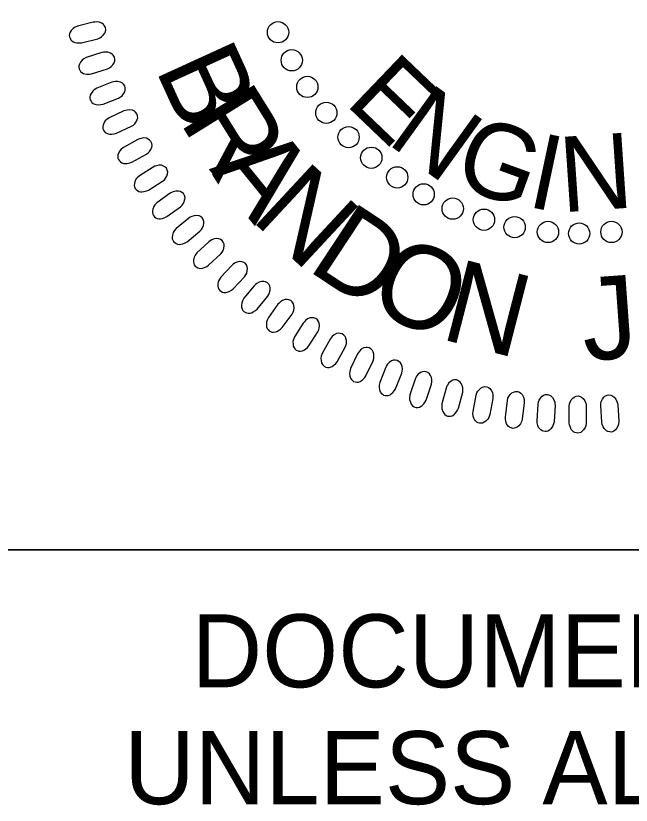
# Model space of a CAD drawing. Extents: x 505602 to 527661, y 418813 to 494436.
# Drawn here: x 507076.9 to 507123.2, y 484026.9 to 484086.4 of the extents above; entities that cross this region are included whole.
import ezdxf

# ---------------------------------------------------------------- set-up
doc = ezdxf.new("R2010")
doc.units = 0
for name, color, linetype in [('Sheet PE Seal Cell', 7, 'Continuous'), ('Sheet Profile CELL', 7, 'Continuous'), ('Sheet Sticker Exception Certification CELL', 7, 'Continuous')]:
    doc.layers.add(name, color=color, linetype=linetype)

msp = doc.modelspace()

# ---------------------------------------------------------------- linework, layer by layer
at = {"layer": 'Sheet PE Seal Cell'}
for points in [[(507082.689, 484085.9), (507081.501, 484085.595), (507081.298, 484085.504), (507081.175, 484085.42), (507081.039, 484085.269), (507080.957, 484085.147), (507080.907, 484085.019), (507080.895, 484084.908), (507080.903, 484084.794), (507080.95, 484084.691), (507081.009, 484084.582), (507081.093, 484084.495), (507081.216, 484084.419), (507081.308, 484084.38), (507081.469, 484084.353), (507081.658, 484084.339), (507081.818, 484084.357), (507083.037, 484084.662), (507083.196, 484084.726), (507083.32, 484084.804), (507083.452, 484084.931), (507083.56, 484085.074), (507083.613, 484085.187), (507083.632, 484085.355), (507083.614, 484085.505), (507083.538, 484085.639), (507083.464, 484085.728), (507083.336, 484085.827), (507083.142, 484085.9), (507082.951, 484085.921), (507082.818, 484085.917)], [(507083.343, 484083.616), (507082.176, 484083.237), (507081.979, 484083.134), (507081.862, 484083.042), (507081.735, 484082.882), (507081.661, 484082.756), (507081.62, 484082.625), (507081.615, 484082.513), (507081.63, 484082.4), (507081.684, 484082.3), (507081.749, 484082.195), (507081.838, 484082.114), (507081.966, 484082.046), (507082.059, 484082.013), (507082.223, 484081.995), (507082.412, 484081.994), (507082.571, 484082.022), (507083.768, 484082.403), (507083.922, 484082.477), (507084.042, 484082.562), (507084.165, 484082.697), (507084.263, 484082.846), (507084.31, 484082.963), (507084.318, 484083.131), (507084.291, 484083.28), (507084.207, 484083.409), (507084.127, 484083.494), (507083.993, 484083.584), (507083.795, 484083.645), (507083.603, 484083.654), (507083.471, 484083.642)], [(507084.102, 484081.379), (507082.961, 484080.928), (507082.77, 484080.812), (507082.659, 484080.713), (507082.543, 484080.546), (507082.477, 484080.415), (507082.444, 484080.281), (507082.446, 484080.17), (507082.468, 484080.058), (507082.528, 484079.961), (507082.6, 484079.861), (507082.693, 484079.786), (507082.825, 484079.725), (507082.921, 484079.699), (507083.086, 484079.691), (507083.274, 484079.702), (507083.431, 484079.739), (507084.602, 484080.194), (507084.752, 484080.278), (507084.865, 484080.371), (507084.98, 484080.513), (507085.069, 484080.668), (507085.108, 484080.788), (507085.105, 484080.956), (507085.069, 484081.103), (507084.977, 484081.227), (507084.892, 484081.306), (507084.753, 484081.388), (507084.551, 484081.436), (507084.359, 484081.433), (507084.228, 484081.412)], [(507085.001, 484079.22), (507083.891, 484078.698), (507083.709, 484078.57), (507083.604, 484078.464), (507083.499, 484078.29), (507083.441, 484078.155), (507083.416, 484078.02), (507083.425, 484077.908), (507083.454, 484077.798), (507083.52, 484077.706), (507083.598, 484077.61), (507083.697, 484077.541), (507083.832, 484077.489), (507083.929, 484077.468), (507084.093, 484077.471), (507084.281, 484077.494), (507084.435, 484077.541), (507085.576, 484078.068), (507085.719, 484078.161), (507085.827, 484078.261), (507085.932, 484078.41), (507086.012, 484078.571), (507086.043, 484078.693), (507086.03, 484078.861), (507085.984, 484079.005), (507085.884, 484079.122), (507085.794, 484079.196), (507085.651, 484079.269), (507085.446, 484079.304), (507085.255, 484079.289), (507085.125, 484079.261)], [(507086.049, 484077.071), (507084.973, 484076.48), (507084.799, 484076.342), (507084.702, 484076.229), (507084.607, 484076.049), (507084.558, 484075.91), (507084.542, 484075.774), (507084.557, 484075.663), (507084.594, 484075.555), (507084.666, 484075.467), (507084.75, 484075.377), (507084.852, 484075.314), (507084.99, 484075.27), (507085.089, 484075.256), (507085.252, 484075.269), (507085.438, 484075.303), (507085.589, 484075.36), (507086.694, 484075.958), (507086.832, 484076.06), (507086.932, 484076.167), (507087.029, 484076.322), (507087.097, 484076.487), (507087.121, 484076.611), (507087.097, 484076.777), (507087.043, 484076.918), (507086.936, 484077.03), (507086.842, 484077.098), (507086.693, 484077.161), (507086.487, 484077.184), (507086.297, 484077.156), (507086.169, 484077.12)], [(507087.205, 484074.996), (507086.169, 484074.339), (507086.003, 484074.19), (507085.914, 484074.072), (507085.83, 484073.885), (507085.79, 484073.745), (507085.783, 484073.607), (507085.805, 484073.498), (507085.848, 484073.392), (507085.926, 484073.309), (507086.015, 484073.224), (507086.121, 484073.167), (507086.261, 484073.132), (507086.36, 484073.124), (507086.523, 484073.148), (507086.707, 484073.194), (507086.853, 484073.26), (507087.919, 484073.926), (507088.05, 484074.036), (507088.144, 484074.15), (507088.23, 484074.31), (507088.288, 484074.479), (507088.304, 484074.605), (507088.27, 484074.769), (507088.207, 484074.906), (507088.093, 484075.011), (507087.995, 484075.072), (507087.842, 484075.126), (507087.635, 484075.137), (507087.447, 484075.097), (507087.322, 484075.053)], [(507088.482, 484073.021), (507087.488, 484072.3), (507087.333, 484072.141), (507087.25, 484072.017), (507087.179, 484071.826), (507087.148, 484071.683), (507087.149, 484071.546), (507087.178, 484071.438), (507087.228, 484071.335), (507087.31, 484071.256), (507087.405, 484071.177), (507087.515, 484071.127), (507087.657, 484071.102), (507087.756, 484071.1), (507087.917, 484071.133), (507088.097, 484071.19), (507088.24, 484071.266), (507089.261, 484071.998), (507089.385, 484072.116), (507089.471, 484072.235), (507089.548, 484072.401), (507089.595, 484072.573), (507089.603, 484072.699), (507089.559, 484072.861), (507089.487, 484072.994), (507089.367, 484073.091), (507089.265, 484073.147), (507089.11, 484073.192), (507088.903, 484073.188), (507088.717, 484073.137), (507088.595, 484073.085)], [(507089.885, 484071.14), (507088.939, 484070.358), (507088.794, 484070.19), (507088.72, 484070.061), (507088.661, 484069.866), (507088.638, 484069.721), (507088.648, 484069.584), (507088.684, 484069.478), (507088.74, 484069.379), (507088.827, 484069.305), (507088.926, 484069.232), (507089.039, 484069.189), (507089.182, 484069.173), (507089.282, 484069.177), (507089.44, 484069.221), (507089.616, 484069.289), (507089.754, 484069.373), (507090.727, 484070.168), (507090.844, 484070.293), (507090.922, 484070.417), (507090.988, 484070.588), (507091.025, 484070.763), (507091.024, 484070.889), (507090.97, 484071.048), (507090.89, 484071.176), (507090.764, 484071.265), (507090.659, 484071.314), (507090.501, 484071.349), (507090.295, 484071.333), (507090.113, 484071.271), (507089.994, 484071.211)], [(507091.395, 484069.369), (507090.5, 484068.53), (507090.366, 484068.353), (507090.3, 484068.219), (507090.253, 484068.021), (507090.24, 484067.875), (507090.258, 484067.739), (507090.301, 484067.635), (507090.363, 484067.54), (507090.454, 484067.472), (507090.558, 484067.405), (507090.673, 484067.37), (507090.818, 484067.362), (507090.916, 484067.372), (507091.072, 484067.426), (507091.244, 484067.505), (507091.375, 484067.597), (507092.296, 484068.452), (507092.405, 484068.585), (507092.476, 484068.713), (507092.531, 484068.887), (507092.556, 484069.065), (507092.548, 484069.19), (507092.484, 484069.346), (507092.396, 484069.468), (507092.265, 484069.55), (507092.157, 484069.592), (507091.997, 484069.617), (507091.792, 484069.588), (507091.614, 484069.514), (507091.5, 484069.447)], [(507093.131, 484067.591), (507092.29, 484066.697), (507092.167, 484066.512), (507092.11, 484066.374), (507092.075, 484066.174), (507092.071, 484066.026), (507092.098, 484065.892), (507092.147, 484065.792), (507092.215, 484065.7), (507092.31, 484065.638), (507092.419, 484065.578), (507092.535, 484065.549), (507092.68, 484065.551), (507092.778, 484065.568), (507092.93, 484065.631), (507093.096, 484065.721), (507093.222, 484065.821), (507094.088, 484066.733), (507094.187, 484066.871), (507094.25, 484067.004), (507094.294, 484067.181), (507094.308, 484067.36), (507094.292, 484067.484), (507094.219, 484067.636), (507094.123, 484067.753), (507093.987, 484067.826), (507093.876, 484067.861), (507093.716, 484067.876), (507093.513, 484067.834), (507093.34, 484067.749), (507093.23, 484067.675)], [(507094.821, 484066.061), (507094.038, 484065.116), (507093.927, 484064.923), (507093.878, 484064.782), (507093.856, 484064.58), (507093.862, 484064.433), (507093.897, 484064.3), (507093.952, 484064.203), (507094.026, 484064.115), (507094.124, 484064.06), (507094.236, 484064.007), (507094.354, 484063.986), (507094.499, 484063.997), (507094.596, 484064.019), (507094.743, 484064.092), (507094.903, 484064.192), (507095.023, 484064.3), (507095.83, 484065.264), (507095.921, 484065.409), (507095.974, 484065.546), (507096.008, 484065.725), (507096.011, 484065.904), (507095.986, 484066.028), (507095.903, 484066.174), (507095.801, 484066.285), (507095.661, 484066.349), (507095.547, 484066.377), (507095.386, 484066.381), (507095.187, 484066.327), (507095.019, 484066.232), (507094.914, 484066.151)], [(507096.601, 484064.66), (507095.88, 484063.668), (507095.781, 484063.469), (507095.741, 484063.325), (507095.732, 484063.121), (507095.747, 484062.975), (507095.79, 484062.845), (507095.851, 484062.751), (507095.93, 484062.669), (507096.033, 484062.62), (507096.148, 484062.574), (507096.267, 484062.56), (507096.41, 484062.58), (507096.506, 484062.608), (507096.648, 484062.691), (507096.802, 484062.8), (507096.914, 484062.916), (507097.659, 484063.928), (507097.74, 484064.078), (507097.786, 484064.218), (507097.808, 484064.399), (507097.8, 484064.578), (507097.767, 484064.7), (507097.676, 484064.841), (507097.566, 484064.945), (507097.422, 484065.001), (507097.308, 484065.021), (507097.147, 484065.016), (507096.95, 484064.949), (507096.79, 484064.843), (507096.69, 484064.756)], [(507098.503, 484063.247), (507097.846, 484062.211), (507097.759, 484062.006), (507097.728, 484061.86), (507097.732, 484061.657), (507097.756, 484061.513), (507097.808, 484061.385), (507097.874, 484061.295), (507097.959, 484061.218), (507098.063, 484061.175), (507098.181, 484061.136), (507098.301, 484061.131), (507098.443, 484061.159), (507098.536, 484061.194), (507098.673, 484061.284), (507098.82, 484061.403), (507098.924, 484061.526), (507099.604, 484062.583), (507099.676, 484062.738), (507099.713, 484062.88), (507099.723, 484063.063), (507099.703, 484063.241), (507099.663, 484063.36), (507099.564, 484063.495), (507099.448, 484063.592), (507099.3, 484063.638), (507099.185, 484063.652), (507099.025, 484063.637), (507098.833, 484063.558), (507098.679, 484063.442), (507098.585, 484063.349)], [(507100.521, 484062.032), (507099.93, 484060.957), (507099.857, 484060.747), (507099.835, 484060.599), (507099.852, 484060.396), (507099.884, 484060.253), (507099.944, 484060.129), (507100.016, 484060.044), (507100.105, 484059.972), (507100.212, 484059.936), (507100.332, 484059.904), (507100.452, 484059.906), (507100.592, 484059.944), (507100.683, 484059.984), (507100.814, 484060.083), (507100.953, 484060.212), (507101.05, 484060.34), (507101.662, 484061.438), (507101.723, 484061.597), (507101.751, 484061.742), (507101.75, 484061.924), (507101.72, 484062.101), (507101.673, 484062.218), (507101.564, 484062.346), (507101.442, 484062.435), (507101.292, 484062.472), (507101.176, 484062.479), (507101.017, 484062.453), (507100.831, 484062.362), (507100.685, 484062.237), (507100.596, 484062.138)], [(507102.58, 484060.925), (507102.058, 484059.815), (507101.998, 484059.601), (507101.986, 484059.452), (507102.015, 484059.251), (507102.056, 484059.11), (507102.124, 484058.991), (507102.201, 484058.91), (507102.295, 484058.844), (507102.404, 484058.815), (507102.525, 484058.79), (507102.645, 484058.8), (507102.783, 484058.846), (507102.871, 484058.892), (507102.995, 484058.999), (507103.126, 484059.136), (507103.215, 484059.27), (507103.757, 484060.404), (507103.808, 484060.568), (507103.827, 484060.713), (507103.814, 484060.895), (507103.773, 484061.069), (507103.718, 484061.183), (507103.602, 484061.304), (507103.474, 484061.386), (507103.323, 484061.414), (507103.206, 484061.413), (507103.049, 484061.377), (507102.869, 484061.275), (507102.732, 484061.14), (507102.65, 484061.036)], [(507104.708, 484059.917), (507104.256, 484058.776), (507104.21, 484058.559), (507104.207, 484058.41), (507104.249, 484058.21), (507104.298, 484058.073), (507104.374, 484057.957), (507104.456, 484057.882), (507104.553, 484057.822), (507104.664, 484057.799), (507104.787, 484057.783), (507104.906, 484057.799), (507105.04, 484057.854), (507105.125, 484057.906), (507105.243, 484058.02), (507105.364, 484058.165), (507105.444, 484058.305), (507105.914, 484059.471), (507105.956, 484059.637), (507105.965, 484059.783), (507105.941, 484059.964), (507105.888, 484060.135), (507105.827, 484060.246), (507105.703, 484060.359), (507105.571, 484060.433), (507105.418, 484060.45), (507105.302, 484060.442), (507105.147, 484060.397), (507104.974, 484060.283), (507104.845, 484060.141), (507104.77, 484060.032)], [(507106.917, 484059.015), (507106.537, 484057.848), (507106.505, 484057.628), (507106.511, 484057.479), (507106.565, 484057.283), (507106.624, 484057.149), (507106.706, 484057.038), (507106.793, 484056.968), (507106.894, 484056.914), (507107.006, 484056.899), (507107.13, 484056.89), (507107.247, 484056.914), (507107.378, 484056.977), (507107.459, 484057.034), (507107.57, 484057.156), (507107.682, 484057.308), (507107.753, 484057.453), (507108.149, 484058.645), (507108.18, 484058.814), (507108.18, 484058.96), (507108.144, 484059.14), (507108.081, 484059.307), (507108.013, 484059.413), (507107.882, 484059.519), (507107.746, 484059.584), (507107.592, 484059.592), (507107.477, 484059.576), (507107.325, 484059.522), (507107.159, 484059.398), (507107.039, 484059.247), (507106.971, 484059.133)], [(507109.25, 484058.342), (507108.944, 484057.154), (507108.926, 484056.933), (507108.941, 484056.784), (507109.008, 484056.591), (507109.074, 484056.461), (507109.164, 484056.356), (507109.255, 484056.291), (507109.358, 484056.244), (507109.472, 484056.236), (507109.595, 484056.235), (507109.711, 484056.266), (507109.837, 484056.337), (507109.915, 484056.399), (507110.018, 484056.528), (507110.12, 484056.687), (507110.182, 484056.836), (507110.502, 484058.05), (507110.522, 484058.22), (507110.513, 484058.367), (507110.466, 484058.544), (507110.393, 484058.707), (507110.318, 484058.808), (507110.181, 484058.906), (507110.042, 484058.962), (507109.886, 484058.96), (507109.773, 484058.938), (507109.625, 484058.873), (507109.467, 484058.739), (507109.357, 484058.581), (507109.296, 484058.464)], [(507112.772, 484057.554), (507112.541, 484056.349), (507112.463, 484056.141), (507112.386, 484056.013), (507112.244, 484055.868), (507112.128, 484055.779), (507112.003, 484055.721), (507111.892, 484055.701), (507111.778, 484055.703), (507111.673, 484055.744), (507111.56, 484055.795), (507111.469, 484055.874), (507111.385, 484055.991), (507111.341, 484056.081), (507111.303, 484056.241), (507111.278, 484056.428), (507111.286, 484056.589), (507111.514, 484057.825), (507111.568, 484057.987), (507111.639, 484058.116), (507111.757, 484058.256), (507111.893, 484058.372), (507112.003, 484058.432), (507112.168, 484058.461), (507112.32, 484058.452), (507112.458, 484058.385), (507112.552, 484058.316), (507112.658, 484058.196), (507112.743, 484058.006), (507112.776, 484057.817), (507112.781, 484057.685)], [(507115.138, 484057.228), (507114.983, 484056.011), (507114.919, 484055.798), (507114.849, 484055.666), (507114.717, 484055.512), (507114.607, 484055.415), (507114.485, 484055.35), (507114.377, 484055.324), (507114.263, 484055.318), (507114.155, 484055.352), (507114.039, 484055.397), (507113.943, 484055.469), (507113.852, 484055.582), (507113.802, 484055.668), (507113.754, 484055.825), (507113.718, 484056.01), (507113.715, 484056.171), (507113.866, 484057.419), (507113.909, 484057.584), (507113.972, 484057.717), (507114.08, 484057.864), (507114.209, 484057.989), (507114.316, 484058.055), (507114.479, 484058.095), (507114.63, 484058.096), (507114.773, 484058.038), (507114.871, 484057.975), (507114.985, 484057.861), (507115.081, 484057.678), (507115.126, 484057.49), (507115.139, 484057.358)], [(507117.455, 484057.031), (507117.377, 484055.806), (507117.326, 484055.59), (507117.265, 484055.453), (507117.143, 484055.291), (507117.039, 484055.187), (507116.922, 484055.116), (507116.815, 484055.082), (507116.701, 484055.07), (507116.591, 484055.097), (507116.474, 484055.134), (507116.373, 484055.2), (507116.275, 484055.306), (507116.22, 484055.39), (507116.162, 484055.543), (507116.114, 484055.726), (507116.102, 484055.887), (507116.173, 484057.141), (507116.207, 484057.309), (507116.261, 484057.446), (507116.36, 484057.599), (507116.48, 484057.732), (507116.583, 484057.805), (507116.743, 484057.855), (507116.894, 484057.865), (507117.041, 484057.816), (507117.141, 484057.759), (507117.262, 484057.652), (507117.37, 484057.475), (507117.427, 484057.291), (507117.448, 484057.161)], [(507119.808, 484056.959), (507119.808, 484055.732), (507119.77, 484055.513), (507119.718, 484055.373), (507119.606, 484055.203), (507119.508, 484055.094), (507119.396, 484055.014), (507119.292, 484054.974), (507119.18, 484054.955), (507119.068, 484054.974), (507118.948, 484055.004), (507118.843, 484055.063), (507118.738, 484055.164), (507118.679, 484055.244), (507118.611, 484055.393), (507118.552, 484055.573), (507118.529, 484055.732), (507118.522, 484056.989), (507118.545, 484057.158), (507118.59, 484057.298), (507118.679, 484057.458), (507118.791, 484057.597), (507118.889, 484057.677), (507119.046, 484057.737), (507119.196, 484057.756), (507119.345, 484057.717), (507119.45, 484057.667), (507119.577, 484057.568), (507119.696, 484057.398), (507119.764, 484057.218), (507119.793, 484057.088)], [(507122.175, 484057.081), (507122.251, 484055.857), (507122.228, 484055.635), (507122.185, 484055.493), (507122.083, 484055.316), (507121.994, 484055.201), (507121.886, 484055.114), (507121.785, 484055.068), (507121.674, 484055.041), (507121.561, 484055.055), (507121.44, 484055.077), (507121.331, 484055.13), (507121.22, 484055.223), (507121.156, 484055.299), (507121.08, 484055.444), (507121.009, 484055.619), (507120.976, 484055.777), (507120.89, 484057.031), (507120.902, 484057.201), (507120.938, 484057.343), (507121.018, 484057.508), (507121.121, 484057.655), (507121.213, 484057.74), (507121.366, 484057.81), (507121.514, 484057.839), (507121.665, 484057.808), (507121.773, 484057.765), (507121.906, 484057.674), (507122.036, 484057.512), (507122.115, 484057.337), (507122.153, 484057.21)]]:
    msp.add_lwpolyline(points, close=True, dxfattribs=at)
for centre in [(507096.606, 484085.148), (507097.641, 484083.036), (507098.81, 484081.032), (507100.242, 484079.08), (507101.914, 484077.247), (507103.625, 484075.693), (507105.576, 484074.218), (507107.566, 484072.943), (507109.755, 484071.866), (507112.104, 484071.029), (507114.413, 484070.47), (507116.921, 484070.111), (507119.27, 484069.991), (507121.699, 484070.109)]:
    msp.add_circle(centre, 0.801, dxfattribs=at)
at = {"layer": 'Sheet Profile CELL'}
msp.add_lwpolyline([(507069.03, 484158.662), (507169.08, 484158.662), (507169.08, 484046.162), (507069.03, 484046.162)], close=True, dxfattribs=at)
at = {"layer": 'Sheet Sticker Exception Certification CELL'}
msp.add_line((507069.03, 484046.162), (507269.067, 484046.162), dxfattribs=at)
msp.add_line((507069.03, 484046.162), (507269.067, 484046.162), dxfattribs=at)

# ---------------------------------------------------------------- texts
at = {"layer": 'Sheet PE Seal Cell'}
for s, height, rotation, p in [('B', 6.236, 294.5897, (507087.323, 484082.419)), ('E', 5.669, 316.26559, (507101.563, 484079.798)), ('R', 6.236, 301.86473, (507089.134, 484078.463)), ('N', 5.669, 324.20538, (507104.698, 484076.843)), ('G', 5.669, 340.08498, (507109.592, 484073.744)), ('I', 5.669, 348.02477, (507115.221, 484072.055)), ('N', 5.669, 3.90437, (507117.974, 484071.582)), ('A', 6.236, 308.98157, (507091.377, 484074.845)), ('N', 6.236, 317.09274, (507094.456, 484071.097)), ('D', 6.236, 326.58243, (507098.686, 484067.315)), ('O', 6.236, 335.45066, (507103.152, 484064.457)), ('N', 6.236, 345.5505, (507108.704, 484062.086)), ('J', 6.236, 4.1457, (507119.655, 484060.393))]:
    msp.add_text(s, height=height, rotation=rotation, dxfattribs=at).set_placement(p)
at = {"layer": 'Sheet Sticker Exception Certification CELL'}
for s, p in [('DOCUMENT NOT CONSIDERED FINAL', (507090.101, 484035.816)), ('DOCUMENT NOT CONSIDERED FINAL', (507090.101, 484035.816)), ('UNLESS ALL SIGNATURES COMPLETED', (507085.03, 484027.016)), ('UNLESS ALL SIGNATURES COMPLETED', (507085.03, 484027.016))]:
    msp.add_text(s, height=5.5, dxfattribs=at).set_placement(p)

doc.saveas('drawing.dxf')
